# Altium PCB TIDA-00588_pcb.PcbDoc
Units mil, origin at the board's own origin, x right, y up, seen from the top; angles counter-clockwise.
Board outline 4010.03 x 1510.03 mil, 2 copper layers (Top Layer, Bottom Layer), stack 62 mil thick; 90 components, 39 nets, 274 pads, 4 vias.
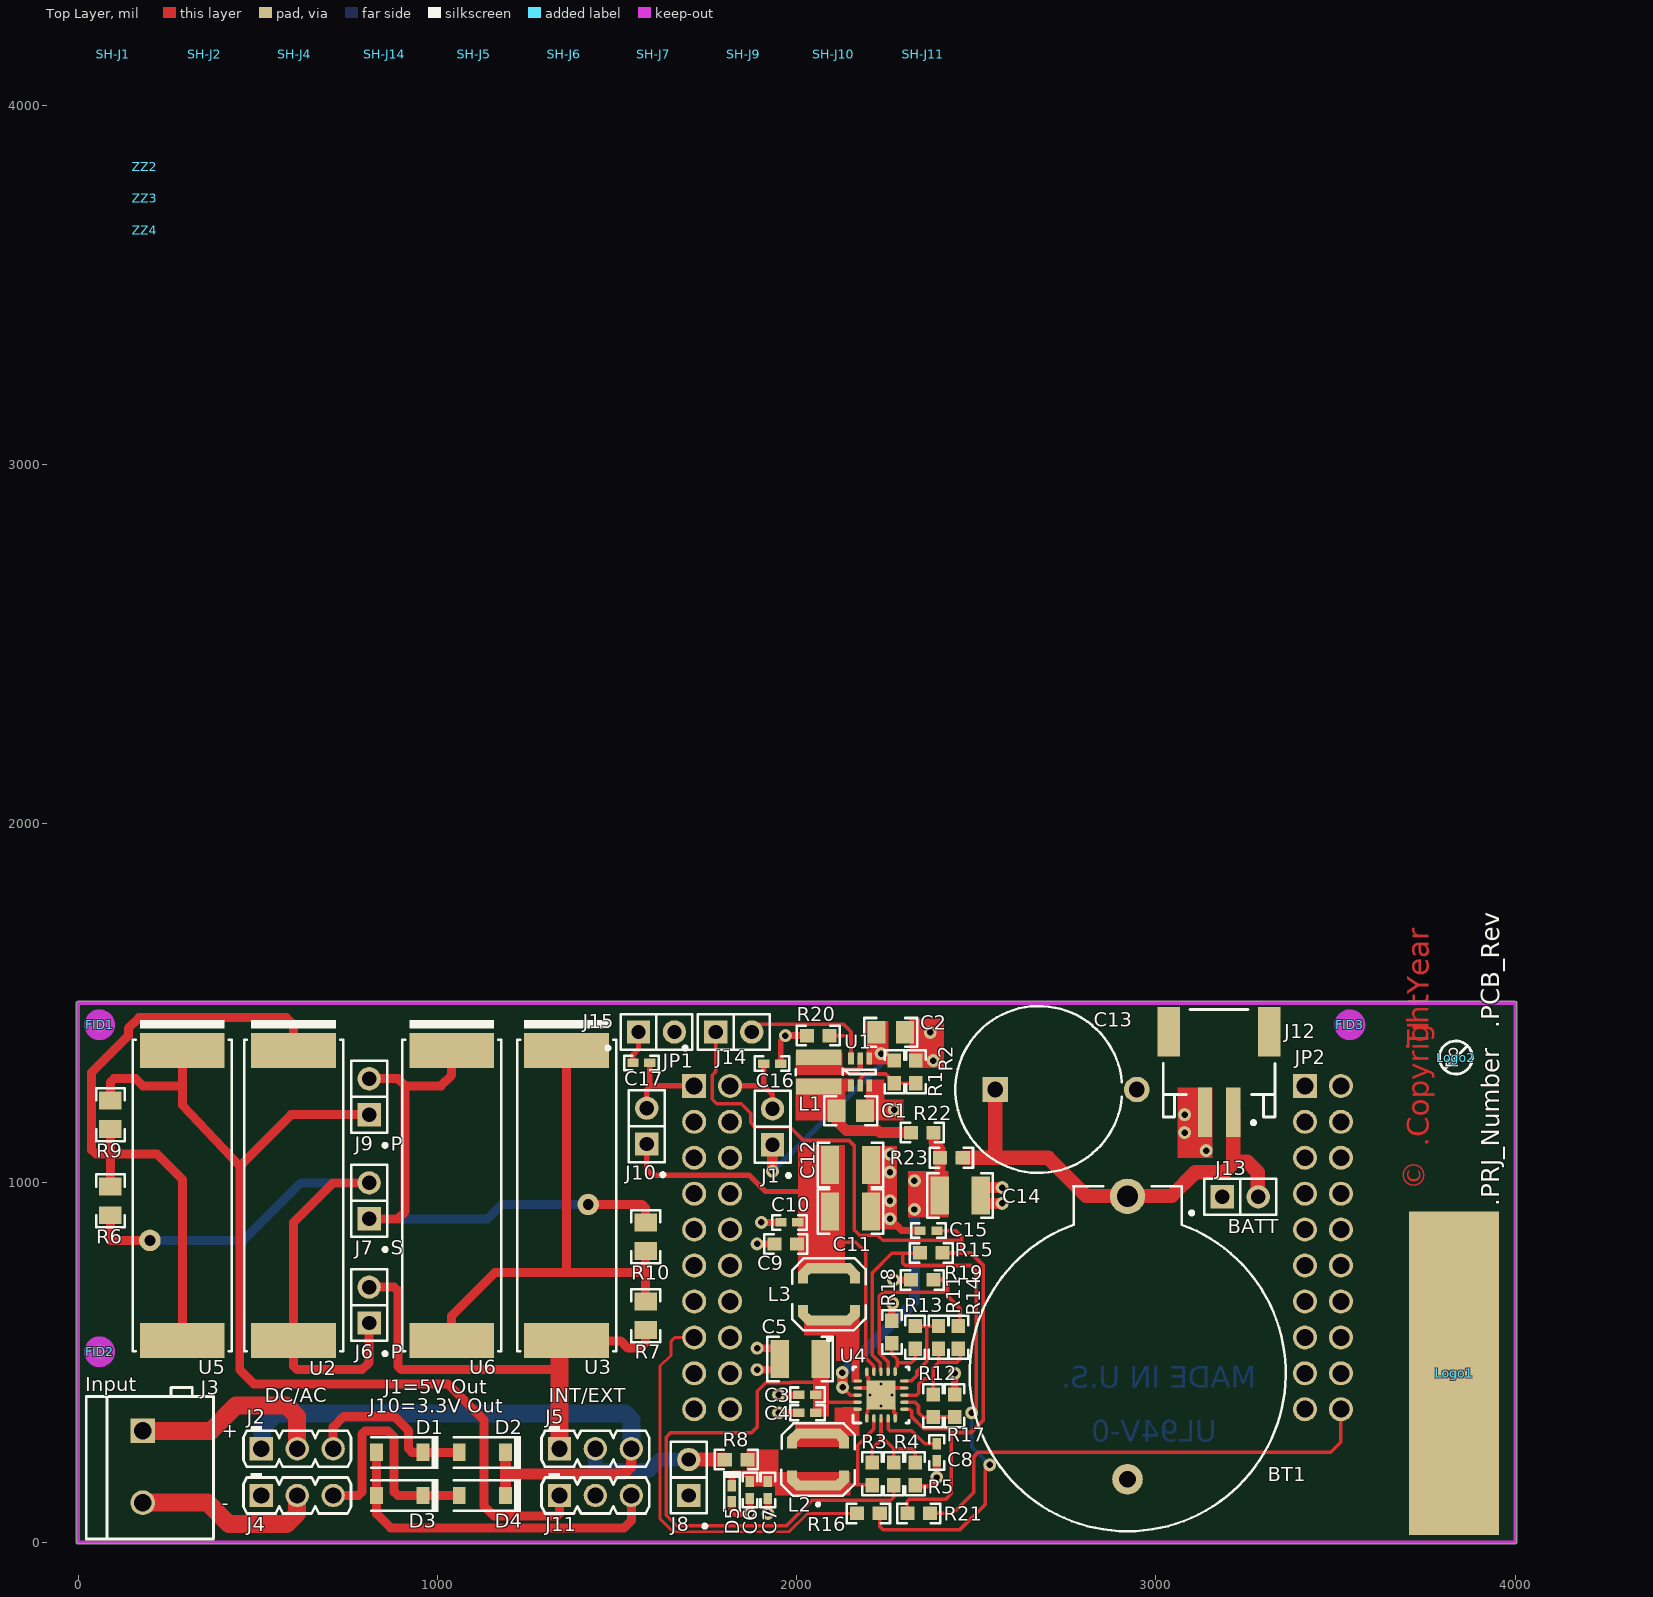
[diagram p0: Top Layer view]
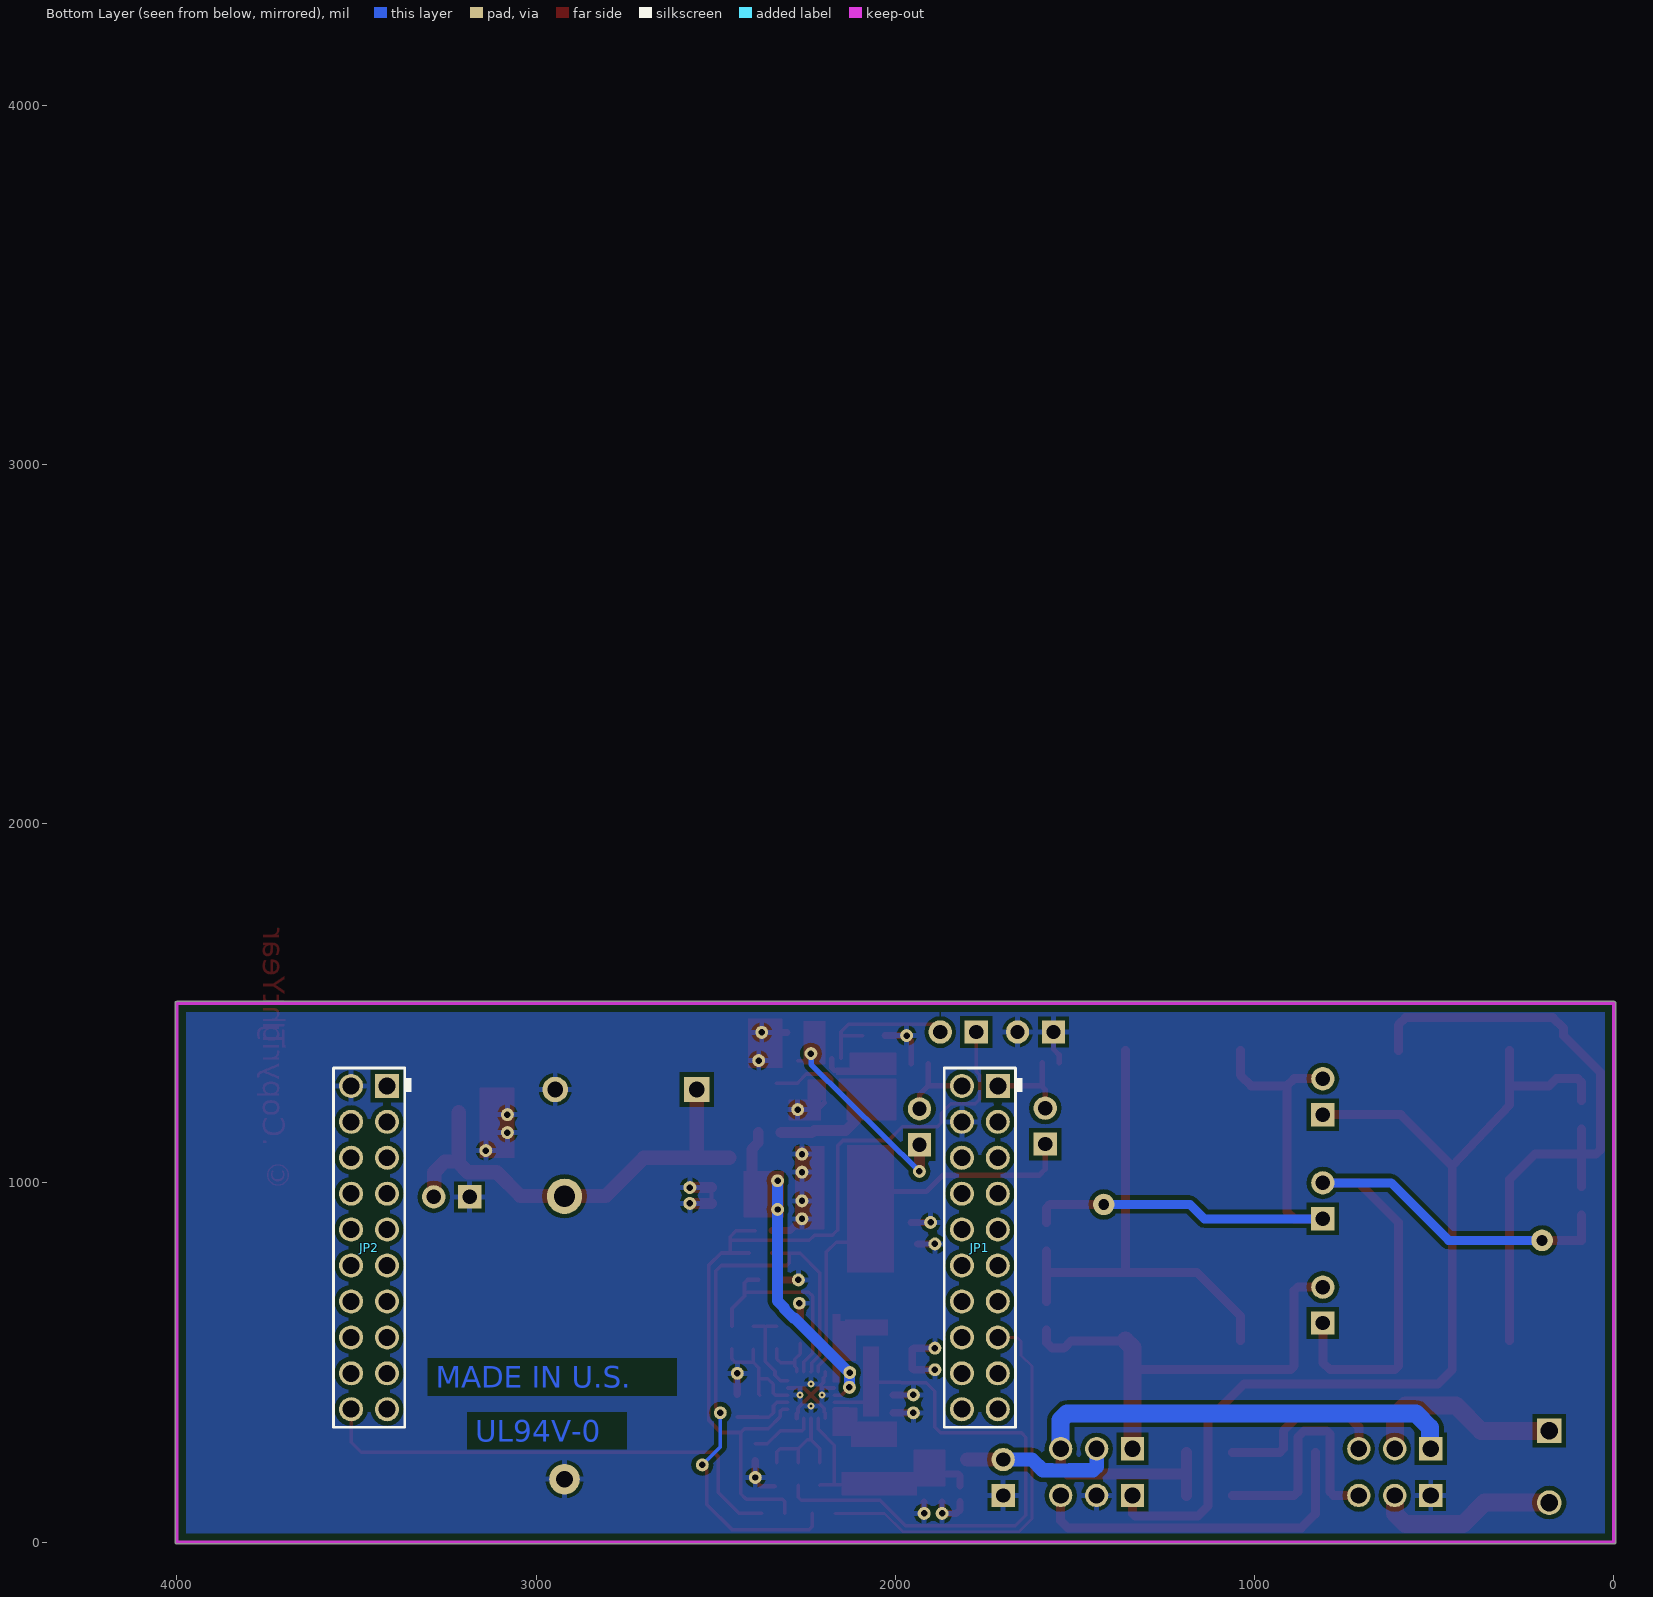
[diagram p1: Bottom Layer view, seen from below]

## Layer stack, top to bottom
Top Solder: solder mask 0.4, Solder Resist, Dk 3.5
Top Layer: signal copper 1.4
Dielectric1: core 59.2, FR-4, Dk 4.8
Bottom Layer: signal copper 1.4
Bottom Solder: solder mask 0.4, Solder Resist, Dk 3.5

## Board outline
0,-5.02 cw(c0,0) -5.01,0 -5.01,1500 cw(c0,1500) 0,1505.01 4000,1505.01 cw(c4000,1500) 4005.02,1500 4005.02,0 cw(c4000,0) 4000,-5.02

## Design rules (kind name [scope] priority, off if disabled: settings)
AcuteAngle [All] p1: minimum=4.50000000000000E+0001 checktracksonly=FALSE
AssemblyTestPointUsage [All] p1: valid=2
Clearance Clearance_Keepouts [((IsTrack Or IsArc) And Not InPoly) And IsFree and IsKeepOut vs ((IsTrack Or IsArc) And Not InPoly) And IsFree and IsKeepOut] p1: gap=0
Clearance Clearance_BoardEdge_MountingHoles [OnCopper and InComponentClass('Mounting Holes') vs IsKeepOut] p2: gap=40
Clearance Clearance_BoardEdge_Poly [OnCopper and InPoly vs IsKeepOut] p3: gap=20
Clearance Clearance_BoardEdge [OnCopper and Not InComponentClass('Logo') and not InComponentClass('FiducialMark') and not InRegion(1000,500,4000,800) and Not IsKeepout vs IsKeepOut] p4: gap=20 except(40: Track-SMDPad Arc-SMDPad SMDPad-SMDPad)
Clearance Clearance_Poly [InPolygon] p5: gap=12
Clearance [All] p6: gap=8
ComponentClearance ComponentClearance_MountingHoles_FiducialMarks [InComponentClass('Mounting Holes') vs InComponentClass('FiducialMark')] p1: gap=50 collisioncheckmode=3 verticalgap=10 showdistances=FALSE
ComponentClearance ComponentClearance_Shunt [InComponentClass('Header') vs InComponentClass('Shunt')] p2: gap=0 collisioncheckmode=3 verticalgap=0 showdistances=FALSE
ComponentClearance ComponentClearance_Logo [InComponentClass('Logo')] p3: gap=50 collisioncheckmode=3 verticalgap=10 showdistances=FALSE
ComponentClearance ComponentClearance_ScrewToNut [(HasFootprint('NY PMS 440 0025 PH')) vs (HasFootprint('Keystone_1902C'))] p4: gap=5 collisioncheckmode=3 verticalgap=10 showdistances=FALSE
ComponentClearance ComponentClearance_MountingHoles [InComponentClass('Mounting Holes')] p5: gap=20 collisioncheckmode=3 verticalgap=100000 showdistances=FALSE
ComponentClearance ComponentClearance_SmallPassives [HasFootprint('0201*') or HasFootprint('0402*') or HasFootprint('0508') or HasFootprint('0603*') or HasFootprint('0612') or HasFootprint('0805*') or HasFootprint('0815*') or HasFootprint('0830*') or HasFootprint('1206*') or HasFootprint('1210*') or HasFootprint('1808*') or HasFootprint('1812*') or HasFootprint('1825*') or HasFootprint('2010*') or HasFootprint('2220*') or HasFootprint('2225*') or HasFootprint('2512*') or HasFootprint('2728*') or HasFootprint('3518*') vs HasFootprint('0201*') or HasFootprint('0402*') or HasFootprint('0508') or HasFootprint('0603*') or HasFootprint('0612') or HasFootprint('0805*') or HasFootprint('0815*') or HasFootprint('0830*') or HasFootprint('1206*') or HasFootprint('1210*') or HasFootprint('1808*') or HasFootprint('1812*') or HasFootprint('1825*') or HasFootprint('2010*') or HasFootprint('2220*') or HasFootprint('2225*') or HasFootprint('2512*') or HasFootprint('2728*') or HasFootprint('3518*')] p6: gap=12 collisioncheckmode=3 verticalgap=12 showdistances=FALSE
ComponentClearance ComponentClearance_THtoSMT [IsThruComponent vs IsSMTComponent] p7: gap=12 collisioncheckmode=3 verticalgap=12 showdistances=FALSE
ComponentClearance ComponentClearance_THtoTH [IsThruComponent vs IsThruComponent] p8: gap=12 collisioncheckmode=3 verticalgap=12 showdistances=FALSE
ComponentClearance [All] p9: gap=12 collisioncheckmode=3 verticalgap=12 showdistances=FALSE
DiffPairsRouting [All] p1: maxlimit=100 minlimit=10 mostfreqgap=10 toplayer_minwidth=15 toplayer_maxwidth=15 toplayer_prefwidth=15 bottomlayer_minwidth=15 bottomlayer_maxwidth=15 bottomlayer_prefwidth=15 maxuncoupledlength=1000
FabricationTestPointUsage TestPointUsage [All] p1: valid=2 allowmultiple=FALSE
FabricationTestpoint Testpoint [All] p1: side=3 testpointundercomponent=TRUE minsize=40 maxsize=100 preferedsize=60 minholesize=0 maxholesize=40 preferedholesize=32 testpointgrid=1 allowsidetop=TRUE allowsidebottom=TRUE usegrid=TRUE gridtolerance=0.01
FanoutControl Fanout_LCC [IsLCC] p1: bgadir=Out bgaviamode=Centered fanoutstyle=Auto fanoutdirection=Alternating viagrid=1 // Fanout_LCC (Default Rule)
FanoutControl Fanout_BGA [IsBGA] p2: bgadir=Out bgaviamode=Centered fanoutstyle=Auto fanoutdirection=Alternating viagrid=1 // Fanout_BGA (Default Rule)
FanoutControl Fanout_Default [All] p4: bgadir=Out bgaviamode=Centered fanoutstyle=Auto fanoutdirection=Alternating viagrid=1 // Fanout_Default (Default Rule)
FanoutControl Fanout_Small [(CompPinCount < 5)] p5: bgadir=Out bgaviamode=Centered fanoutstyle=Auto fanoutdirection=OutThenIn viagrid=1 // Fanout_Small (Default Rule)
HoleSize [All] p1: absolutevalues=TRUE maxlimit=251 minlimit=8 maxpercent=80.000 minpercent=20.000
MinimumAnnularRing MinimumAnnularRing_ThermalPadVias [IsVia and InAnyComponent] p1: minimumring=5.91
MinimumAnnularRing [All] p2: minimumring=9
MinimumSolderMaskSliver MinimumSolderMaskSliver_Logo [InComponentClass('Logo') vs InComponentClass('Logo')] p1: minsoldermaskwidth=0.7
MinimumSolderMaskSliver [All] p2: minsoldermaskwidth=3.94
PlaneConnect [All] p1: planeconnectstyle=Relief reliefexpansion=10 reliefentries=4 reliefconductorwidth=15 reliefairgap=10
PolygonConnect [All] p1: connectstyle=Relief reliefconductorwidth=15 reliefentries=4 polygonreliefangle="90 Angle" airgapwidth=10
RoutingVias ThermalPadVias [IsVia and InAnyComponent] p1: holewidth=7.87 width=19.68 viastyle="Through Hole" minholewidth=7.87 minwidth=19.68 maxholewidth=12.99 maxwidth=23.62
RoutingVias [All] p2: holewidth=16 width=34 viastyle="Through Hole" minholewidth=7.87 minwidth=26 maxholewidth=40 maxwidth=65
SilkToBoardRegionClearance [Not ((IsComment or IsDesignator) And (Hide <> 'False')) and not InRegion(1000,500,4000,800)] p1:
SilkToSilkClearance SilkToSilkClearance_Pb-FreeLogo [(HasFootprint('Pb-Free_Overlay_Medium') OR HasFootprint('Pb-Free_Overlay_Small')) vs (HasFootprint('Pb-Free_Overlay_Medium') OR HasFootprint('Pb-Free_Overlay_Small'))] p1: silktosilkclearance=0
SilkToSilkClearance [All] p2: silktosilkclearance=5
SilkToSolderMaskClearance "Silk to Solder Mask Opening" [All] p1: minsilkscreentomaskgap=1 clearancetoexposedcopper=FALSE
SolderMaskExpansion [All] p1: expansion=1.97
UnpouredPolygon [All] p1: allowunpoured=FALSE
Width [All] p1: maxlimit=100 minlimit=8 preferedwidth=10 checkconnectedcopper=TRUE
14 further rules are at their usual default settings.

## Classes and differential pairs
component class Shunt: SH-J1 SH-J2 SH-J4 SH-J5 SH-J6 SH-J7 SH-J9 SH-J10 SH-J11 SH-J14
component class TIDA-00588_sch: BT1 C1 C2 C3 C4 C5 C6 C7 C8 C9 C10 C11 C12 C13 C14 C15 C16 C17 D1 D2 D3 D4 D5 J1 J2 J3 J4 J5 J6 J7 J8 J9 J10 J11 J12 J13 J14 J15 JP1 JP2 L1 L2 L3 R1 R2 R3 R4 R5 R6 R7 R8 R9 R10 R11 R12 R13 R14 R15 R16 R17 R18 R19 R20 R21 R22 R23 U1 U2 U3 U4 U5 U6
component class Header: J1 J2 J4 J5 J6 J7 J8 J9 J10 J11 J13 J14 J15
component class Logo: Logo1
component class TIDA-00588_hdw: FID1 FID2 FID3 Logo1 Logo2 SH-J1 SH-J2 SH-J4 SH-J5 SH-J6 SH-J7 SH-J9 SH-J10 SH-J11 SH-J14 ZZ2 ZZ3 ZZ4
component class FiducialMark: FID1 FID2 FID3
component class AssemblyNote: ZZ2 ZZ3 ZZ4

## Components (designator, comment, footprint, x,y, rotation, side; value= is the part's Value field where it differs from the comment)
BT1 "BS-7" BAT_BS-7 2921,569 r270 top
C1 "GRM21BR61A106KE19L" 0805_HV 2151,1201 r180 top
C2 "GRM21BR61A106KE19L" 0805_HV 2262,1419 r0 top
C3 "C1005X5R0J475M050BC" 0402 2030,410 r180 top
C4 "GRM155R71A104KA01D" 0402 2030,360 r180 top
C5 "C1210C107M9PACTU" 1210 2010,510 r180 top
C6 "GRM155R71A104KA01D" 0402 1870,145 r270 top
C7 "C1005X5R0J475M050BC" 0402 1920,145 r270 top
C8 "GRM155R61A103KA01D" 0402 2390,250 r270 top
C9 "CL10A226MP8NUNE" 0603 1970,830 r180 top
C10 "GRM155R71A104KA01D" 0402 1980,890 r180 top
C11 "C1210C107M9PACTU" 1210 2150,920 r0 top
C12 "C1210C107M9PACTU" 1210 2150,1050 r0 top
C13 "DX-5R5H473U" DX-H_1150x500 2750,1260 r0 top
C14 "C1210C107M9PACTU" 1210 2455,965 r0 top
C15 "C1005X5R0J105M" 0402 2366.92,867.31 r180 top
C16 "GRM155R71A104KA01D" 0402 1932,1332 r0 top
C17 "GRM155R71A104KA01D" 0402 1568,1334 r180 top
D1 "MBR0520LT1G" SOD-123 895.53,250 r180 top
D2 "MBR0520LT1G" SOD-123 1125.53,250 r180 top
D3 "MBR0520LT1G" SOD-123 895.53,130 r180 top
D4 "MBR0520LT1G" SOD-123 1125.53,130 r180 top
D5 "BZT52C4V7T-7" SOD-523 1820,135 r270 top
FID1 "Fiducial" Fiducial10-20 60,1440 r0 top
FID2 "Fiducial" Fiducial10-20 60,530 r0 top
FID3 "Fiducial" Fiducial10-20 3540,1440 r0 top
J1 "90120-0122" CONN_90120-0122 1933,1156 r90 top
J2 "61300311121" WURTH_61300311121 610,260 r0 top
J3 "ED120/2DS" CONN_ED120-2DS 180,210 r180 top
J4 "61300311121" WURTH_61300311121 610,130 r0 top
J5 "61300311121" WURTH_61300311121 1440,260 r0 top
J6 "90120-0122" CONN_90120-0122 810,660 r90 top
J7 "90120-0122" CONN_90120-0122 810,950 r90 top
J8 "90120-0122" CONN_90120-0122 1700,180 r90 top
J9 "90120-0122" CONN_90120-0122 810,1240 r90 top
J10 "90120-0122" CONN_90120-0122 1583,1158.14 r90 top
J11 "61300311121" WURTH_61300311121 1440,130 r0 top
J12 "S2B-PH-SM4-TB(LF)(SN)" JST_S2B-PH-SM4-TB 3176,1313 r180 top
J13 "90120-0122" CONN_90120-0122 3235,961 r0 top
J14 "90120-0122" CONN_90120-0122 1825.14,1420 r0 top
J15 "90120-0122" CONN_90120-0122 1610,1420 r0 top
JP1 "CRD-081413-A-G" Major_CRD-081413-A-x 1764.96,820 r0 bottom
JP2 "CRD-081413-A-G" Major_CRD-081413-A-x 3464.96,820 r0 bottom
L1 "EPL3015-472MLB" EPL3015 2062,1309 r90 top
L2 "LPS4018-223MLB" LPS4018 2060,230 r90 top
L3 "LPS4018-103MLB" LPS4018 2090,690 r90 top
Logo1 "Texas Instruments" TI_Stacked_SolderMask_Small 3830,470 r90 top
Logo2 "Pb-Free Symbol" Pb-Free_Overlay_Small 3835,1349 r90 top
R1 "CRCW06031M00FKEA" 0603 2272,1309 r90 top
R2 "CRCW0603110KFKEA" 0603 2332,1309 r270 top
R3 "ERJ-3GEY0R00V" 0603 2210,190 r90 top
R4 "ERJ-3GEY0R00V" 0603 2270,190 r270 top
R5 "ERJ-3GEY0R00V" 0603 2330,190 r90 top
R6 "CRCW08050000Z0EA" 0805_HV 90,950 r270 top
R7 "CRCW08050000Z0EA" 0805_HV 1580,630 r270 top
R8 "ERJ-3GEY0R00V" 0603 1831.5,230 r0 top
R9 "CRCW08050000Z0EA" 0805_HV 90,1190 r270 top
R10 "CRCW08050000Z0EA" 0805_HV 1580,850 r270 top
R11 "CRCW0603374KFKEA" 0603 2395,570 r270 top
R12 "CRCW06037M32FKEA" 0603 2380,380 r90 top
R13 "CRCW06038M25FKEA" 0603 2330,570 r90 top
R14 "CRCW06038M25FKEA" 0603 2450,570 r270 top
R15 "ERJ-3GEY0R00V" 0603 2375,805 r180 top
R16 "ERJ-3GEY0R00V" 0603 2200,80 r180 top
R17 "CRCW06035M62FKEA" 0603 2440,380 r270 top
R18 "CRCW06034M53FKEA" 0603 2265,585 r270 top
R19 "CRCW06034M75FKEA" 0603 2350,730 r180 top
R20 "CRCW06031M00FKEA" 0603 2060,1410 r0 top
R21 "ERJ-3GEY0R00V" 0603 2340,80 r0 top
R22 "ERJ-3GEY0R00V" 0603 2350,1140 r180 top
R23 "ERJ-3GEY0R00V" 0603 2431,1070 r180 top
SH-J1 "969102-0000-DA" SNT-100-BK-G 98,4141 r90 top
SH-J2 "969102-0000-DA" SNT-100-BK-G 353,4141 r90 top
SH-J4 "969102-0000-DA" SNT-100-BK-G 603,4141 r90 top
SH-J5 "969102-0000-DA" SNT-100-BK-G 1103,4141 r90 top
SH-J6 "969102-0000-DA" SNT-100-BK-G 1353,4141 r90 top
SH-J7 "969102-0000-DA" SNT-100-BK-G 1603,4141 r90 top
SH-J9 "969102-0000-DA" SNT-100-BK-G 1853,4141 r90 top
SH-J10 "969102-0000-DA" SNT-100-BK-G 2103,4141 r90 top
SH-J11 "969102-0000-DA" SNT-100-BK-G 2353,4141 r90 top
SH-J14 "969102-0000-DA" SNT-100-BK-G 853,4141 r90 top
U1 "TPS61220DCKR" DCK0006A_N 2177,1309 r90 top
U2 "KXOB22-04X3L" KXOB22-04X3 600,965 r90 top
U3 "KXOB22-04X3L" KXOB22-04X3 1360,965 r90 top
U4 "BQ25570RGRR" RGR0020A 2234.96,409.37 r90 top
U5 "KXOB22-04X3L" KXOB22-04X3 290,965 r90 top
U6 "KXOB22-04X3L" KXOB22-04X3 1040,965 r90 top
ZZ2 "This Assembly Note will show in the PcbDoc and associated outputs" AssemblyNote 185,3829.11 r0 top
ZZ3 "This Assembly Note will show in the PcbDoc and associated outputs" AssemblyNote 185,3740.56 r0 top
ZZ4 "This Assembly Note will show in the PcbDoc and associated outputs" AssemblyNote 185,3652 r0 top

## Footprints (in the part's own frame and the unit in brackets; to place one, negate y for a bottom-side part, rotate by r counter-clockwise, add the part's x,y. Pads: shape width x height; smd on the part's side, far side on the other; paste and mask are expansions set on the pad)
0402 [mm] "0402 from SM-752 data"
  rect 0.8x0.6 smd: 1(-0.6,0) 2(0.6,0)
  silkscreen extent -1.22,-0.52 1.22,0.52, body extent -0.55,-0.3 0.55,0.3, height 0.6
0603 [mm] "0603 from SM-752 data"
  rect 1x0.95 smd: 1(-0.8,0) 2(0.8,0)
  silkscreen extent -1.52,-0.69 1.52,0.69, body extent -0.87,-0.47 0.87,0.47, height 0.85
0805_HV [mil] "0805 with 30mil clearance between pads"
  rect 50x63 smd: 1(-40,0) 2(40,0)
  silkscreen extent -74,-40 74,40, body extent -43,-29 43,29, height 43
1210 [mm] "1210 from SM-752 data"
  rect 1.3x2.7 smd: 1(-1.45,0) 2(1.45,0)
  silkscreen extent -2.32,-1.57 2.32,1.57, body extent -1.7,-1.35 1.7,1.35, height 1.35
AssemblyNote [mil] "Assembly Note"
BAT_BS-7 [mm] "Memory Protection Devices CR2032 battery holder"
  round 2.5 hole 1.5: 1(-10,0)
  round 2.17 hole 1.181: 2(10,0)
  silkscreen extent -10.7,-11.16 13.68,11.18, body extent -10.69,-11.16 13.7,11.16, height 9.02
CONN_90120-0122 [mm] "Molex"
  rect 1.65x1.65 hole 1.016 mask+0: 1(-1.27,0)
  round 1.65 hole 1.016 mask+0: 2(1.27,0)
  silkscreen extent -3.56,-1.27 2.54,1.27, body extent -2.54,-1.27 2.54,1.27, height 9.29
CONN_ED120-2DS [mm] "ONSHORE"
  rect 1.75x1.75 hole 1.25: 1(0,-2.54)
  round 1.75 hole 1.25: 2(0,2.54)
  silkscreen extent -5,-5.6 4,5.12, body extent -5,-5.6 4.15,5.12, height 13.1
DCK0006A_N [mm] "SOT23, 6-Leads, Body 2x1.3mm, Pitch 0.65mm, Lead Span 2.1mm, IPC Medium Density"
  rect 0.85x0.4 smd: 1(-0.95,0.65) 2(-0.95,0) 3(-0.95,-0.65) 4(0.95,-0.65) 5(0.95,0) 6(0.95,0.65)
  silkscreen extent -0.15,-1.1 0.15,1.1, body extent -1.14,-1 1.14,1, height 0.94
DX-H_1150x500 [mm] "Elna horizontal SUPERCAP"
  rect 1.8x1.8 hole 1.1: 1(-5,0)
  round 1.8 hole 1.1: 2(5,0)
  silkscreen extent -7.82,-5.9 3.95,5.9, body extent -7.84,-5.91 5.07,5.91, height 5.5
EPL3015 [mm] "COILCRAFT"
  rect 1.12x3.2 smd: 1(-1.04,0) 2(1.04,0)
  silkscreen extent -0.22,-1.68 0.23,1.65, body extent -1.6,-1.6 1.6,1.6, height 1.55
Fiducial10-20 [mm]
  round 1 smd mask+0.5: 1(0,0)
  Top Layer keep-out circle w1.178: c0,0 r0.5
JST_S2B-PH-SM4-TB [mm] "JST Sales America Inc"
  rect 1x3.5 smd paste+0 mask+0.05: 1(-1,2.95) 2(1,2.95)
  rect 1.6x3.5 smd paste+0 mask+0.05: M1(-3.55,-2.75) M2(3.55,-2.75)
  silkscreen extent -3.95,-4.3 3.95,3.79, body extent -3.95,-4.3 3.95,4.3, height 5.62
KXOB22-04X3 [mm] "IXYS"
  rect 2.5x6 smd: 1(-10.25,0) 2(10.25,0)
  silkscreen extent -11,-3.5 12.4,3.5, body extent -11,-3.5 11,3.5, height 1.81
LPS4018 [mil]
  rect 28x123 smd: 1(-72.5,0) 2(72.5,0)
  rect 35.5x28 smd rot 45: 1(-64,64) 2(64.5,-63.5)
  rect 35.5x28 smd rot 135: 1(-64,-64) 2(64,64)
  rect 31.5x28 smd: 1(-46,72.5) 1(-46,-72.5) 2(46,72.5) 2(46,-72.5)
  silkscreen extent -129,-102 100,102, body extent -81,-81 81,81, height 71
Major_CRD-081413-A-x [mm] "Receptacle, 2.54 mm, 10x2, TH"
  rect 1.7x1.7 hole 1.2: 1(-1.27,-11.43)
  round 1.7 hole 1.2: 2(1.27,-11.43) 3(-1.27,-8.89) 4(1.27,-8.89) 5(-1.27,-6.35) 6(1.27,-6.35) 7(-1.27,-3.81) 8(1.27,-3.81) 9(-1.27,-1.27) 10(1.27,-1.27) 11(-1.27,1.27) 12(1.27,1.27) 13(-1.27,3.81) 14(1.27,3.81) 15(-1.27,6.35) 16(1.27,6.35) 17(-1.27,8.89) 18(1.27,8.89) 19(-1.27,11.43) 20(1.27,11.43)
  silkscreen extent -3,-12.71 2.52,12.71, body extent -2.52,-12.71 2.52,12.71, height 8.64
Pb-Free_Overlay_Small [mil]
  silkscreen extent -46,-46 46,46
RGR0020A [mm] "QFN, 20-Leads, Body 3.5x3.5mm, Pitch 0.5mm, Thermal Pad 2.05x2.05mm, TI Recommended"
  oval 0.6x0.24 smd: 1(-1.65,1) 2(-1.65,0.5) 3(-1.65,0) 4(-1.65,-0.5) 5(-1.65,-1) 11(1.65,-1) 12(1.65,-0.5) 13(1.65,0) 14(1.65,0.5) 15(1.65,1)
  oval 0.24x0.6 smd: 6(-1,-1.65) 7(-0.5,-1.65) 8(0,-1.65) 9(0.5,-1.65) 10(1,-1.65) 16(1,1.65) 17(0.5,1.65) 18(0,1.65) 19(-0.5,1.65) 20(-1,1.65)
  rect 2.05x2.05 smd paste-1.025: 21(0,0)
  silkscreen extent -1.97,-1.97 1.97,1.97, body extent -1.83,-1.83 1.83,1.83, height 1.01
SNT-100-BK-G [mil] "Samtec STEP model"
  round 1 on Mech3: 0(0,0)
  body extent -100,-50 100,50, height 344
SOD-123 [mm] "On Semi recommended land pattern"
  rect 0.915x1.22 smd: 1(-1.637,0) 2(1.637,0)
  silkscreen extent -2.74,-1.17 2.03,1.17, body extent -1.93,-0.9 1.93,0.9, height 1.35
SOD-523 [mm] "NXP Semiconductor recommended land pattern, nominal STEP model"
  rect 0.8x0.6 smd paste-0.05: 1(-0.55,0) 2(0.55,0)
  silkscreen extent -1.6,-0.63 1.2,0.64, body extent -0.8,-0.4 0.8,0.4, height 0.72
TI_Stacked_SolderMask_Small [mil]
  rect 900x250 smd paste-125 mask-125: 0(0,0)
WURTH_61300311121 [mm] "Header, 2.54mm, 3x1, TH"
  rect 1.65x1.65 hole 1.15: 1(-2.54,0)
  round 1.65 hole 1.15: 2(0,0) 3(2.54,0)
  silkscreen extent -3.81,-1.27 3.81,1.6, body extent -3.81,-1.27 3.81,1.27, height 8.54

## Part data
BT1: "Battery Holder, CR2032, Retainer clip, TH"
C1 C2: "CAP, CERM, 10 µF, 10 V, +/- 10%, X5R, 0805"
C3 C7: "CAP, CERM, 4.7 µF, 6.3 V, +/- 20%, X5R, 0402"
C4 C6 C10 C16 C17: "CAP, CERM, 0.1 µF, 10 V, +/- 10%, X7R, 0402"
C5 C11 C12 C14: "CAP, CERM, 100 µF, 6.3 V, +/- 20%, X5R, 1210"
C8: "CAP, CERM, 0.01 µF, 10 V, +/- 10%, X5R, 0402"
C9: "CAP, CERM, 22 µF, 10 V, +/- 20%, X5R, 0603"
C13: "CAP, Electric Double Layer, 47000 µF, 5.5 V, +80/-20%, TH"
C15: "CAP, CERM, 1 µF, 6.3 V, +/- 20%, X5R, 0402"
D1 D2 D3 D4: "Diode, Schottky, 20 V, 0.5 A, SOD-123"
D5: "Diode, Zener, 4.7 V, 300 mW, SOD-523"
FID1 FID2 FID3: "Fiducial mark.  There is nothing to buy or mount."
J1 J6 J7 J8 J9 J10 J13 J14 J15: "Header, 100mil, 2x1, Tin, TH"
J2 J4 J5 J11: "Header, 2.54 mm, 3x1, Gold, TH"
J3: "TERMINAL BLOCK 5.08MM VERT 2POS, TH"
J12: "Header (shrouded), 2mm, 2x1, R/A, SMT"
JP1 JP2: "Receptacle, 2.54 mm, 10x2, Gold, TH"
L1: "Inductor, Shielded, Ferrite, 4.7 µH, 1.2 A, 0.14 ohm, SMD"
L2: "Inductor, Shielded Drum Core, Ferrite, 22 µH, 0.83 A, 0.36 ohm, SMD"
L3: "Inductor, Shielded Drum Core, Ferrite, 10 µH, 1.25 A, 0.2 ohm, SMD"
Logo1: library part TI_Logo, "Texas Instrument Corporate Signature"
Logo2: library part Pb-Free
R1 R20: "RES, 1.00 M, 1%, 0.1 W, 0603"
R2: "RES, 110 k, 1%, 0.1 W, 0603"
R3 R4 R5 R8 R15 R16 R21 R22 R23: "RES, 0, 5%, 0.1 W, 0603"
R6 R7 R9 R10: "RES, 0, 5%, 0.125 W, 0805"
R11: "RES, 374 k, 1%, 0.1 W, 0603"
R12: "RES, 7.32 M, 1%, 0.1 W, 0603"
R13 R14: "RES, 8.25 M, 1%, 0.1 W, 0603"
R17: "RES, 5.62 M, 1%, 0.1 W, 0603"
R18: "RES, 4.53 M, 1%, 0.1 W, 0603"
R19: "RES, 4.75 M, 1%, 0.1 W, 0603"
SH-J1 SH-J2 SH-J4 SH-J5 SH-J6 SH-J7 SH-J9 SH-J10 SH-J11 SH-J14: "Shunt, 100mil, Gold plated, Black"
U1: "LOW INPUT VOLTAGE STEP-UP CONVERTER IN 6 PIN SC-70 PACKAGE, DCK0006A"
U2 U3 U5 U6: "MONOCRYSTALLINE SOLAR CELL, 22MM X 7MM, SMD"
U4: "Ultra Low Power Harvester Power Management IC with Boost Charger, and Nano-Powered Buck Converter, RGR0020A"
ZZ2 ZZ3 ZZ4: library part AssemblyNote

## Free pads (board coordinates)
  round 60 hole 30: 0(200,840) 0(1420,940)
  round 36 hole 18: 1(1870,80) 1(1890,480) 1(1890,540) 1(1890,830) 1(1902,890) 1(1920,80) 1(1933,1032) 1(1950,360) 1(1950,410) 1(1968.98,1410) 1(2127,472) 1(2128,430.88) 1(2235,1360) 1(2260,900) 1(2260,950) 1(2260,1030) 1(2260,1080) 1(2267.58,665) 1(2270,730) 1(2272,1204) 1(2328,926) 1(2328,1006) 1(2372,1419) 1(2380.5,1340.5) 1(2390,180) 1(2440,470) 1(2487.42,360) 1(2537.42,215) 1(2572.09,942.91) 1(2572.09,987.09) 1(3080,1140) 1(3080,1190) 1(3140,1090)

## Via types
v1: diameter 19.68, hole 7.87, Top Layer to Bottom Layer, 4 vias

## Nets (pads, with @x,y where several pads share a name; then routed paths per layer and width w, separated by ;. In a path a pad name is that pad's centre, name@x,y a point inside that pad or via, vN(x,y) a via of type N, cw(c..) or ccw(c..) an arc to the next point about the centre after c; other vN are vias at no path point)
+3.3V: C17.1 J10.2 JP1.1 | length 253.3
  Top Layer w15: J10.2 1583,1260 1591.62,1268.62 ; C17.1 1591.62,1268.62 ; JP1.1 1593,1270 1591.62,1268.62
+5V: C16.1 J1.2 JP1.2 | length 230
  Top Layer w15: JP1.2 1908,1270 ; C16.1 1908.38,1270.38 1908,1270 ; J1.2 1933,1245.76 1908.76,1270 1908,1270
GND: BT1.2 C1.1 C2.2 C3.2 C4.2 C5.2 C6.2 C7.2 C8.2 C9.2 C10.2 C11.2 C12.2 C13.2 C14.2 C15.2 C16.2 C17.2 D5.2 J4.1 J8.1 J11.2 J12.2 J13.1 J15.1 J15.2 JP1.4 JP2.2 pad.1@1870,80 pad.1@1890,480 pad.1@1890,540 pad.1@1890,830 pad.1@1902,890 pad.1@1920,80 pad.1@1950,360 pad.1@1950,410 pad.1@1968.98,1410 pad.1@2260,900 pad.1@2260,950 pad.1@2260,1030 pad.1@2260,1080 pad.1@2267.58,665 pad.1@2270,730 pad.1@2272,1204 pad.1@2372,1419 pad.1@2380.5,1340.5 pad.1@2390,180 pad.1@2440,470 pad.1@2572.09,942.91 pad.1@2572.09,987.09 pad.1@3080,1140 pad.1@3080,1190 pad.1@3140,1090 R2.1 R5.1 R17.1 R18.1 R19.2 R20.1 U1.3 U4.1 U4.5 U4.9 U4.15 U4.17 U4.21 | length 2346.2
  Top Layer w10: U4.17 U4.21@2215.28,429.06 ; U4.1 2195.59,360.16 2198.54,363.11 2198.54,372.95 U4.21 ; U4.15 2195.59,461.86 2200,457.45 2200,444.33 U4.21@2215.28,429.06 ; U4.9 2254.65,429.06 U4.21 ; U4.21@2215.28,429.06 U4.21
  Top Layer w12: U4.21 2271.31,373.02 2271.31,361.31 2274.33,358.29 U4.5 ; R5.1@2335.88,155.54 2375.88,155.54 2390,169.66 pad.1@2390,180 ; C14.2@2512.09,942.91 C14.2 C14.2@2512.09,987.09
  Top Layer w15: C17.2 1544.38,1356.38 1560,1372 J15.1 ; C16.2 1955.62,1395.62 pad.1@1970,1410 ; C1.1@2197.59,1223.41 2217,1204 ; R2.1 pad.1@2380.5,1340.5
  Top Layer w20: D5.2 1820,87.76 1822.24,87.76 1830,80 1870,80 C6.2@1870,111.38 ; pad.1@1890,480 1950,480 1952.91,482.91 C5.2 1952.91,537.09 1950,540 pad.1@1890,540 ; pad.1@1890,830 C9.2 ; pad.1@1910,890 C10.2 ; pad.1@1920,80 C7.2@1920,111.38 ; pad.1@1950,360 C4.2 ; pad.1@1950,410 C3.2 ; pad.1@1970,1410 R20.1 ; pad.1@2260,950 2210,950 2207.09,947.09 C11.2 2207.09,902.91 2210,900 2260,900 2292.69,867.31 C15.2 ; pad.1@2260,1030 2210,1030 2207.09,1032.91 C12.2 2207.09,1077.09 2210,1080 pad.1@2260,1080 ; R18.1@2265,611.5 2265,662.42 pad.1@2267.58,665 ; pad.1@2270,730 R19.2 ; C2.2 pad.1@2372,1419 ; pad.1@2390,180 C8.2 ; R17.1 pad.1@2440,470 ; pad.1@3080,1140 3130.87,1140 J12.2@3140.87,1150 ; pad.1@3080,1190 J12.2@3136.46,1190 ; pad.1@3140,1090 3140.87,1090.87 J12.2@3140.87,1150 ; J12.2@3140.87,1195.59 J12.2@3140.87,1150
  Top Layer w30: C14.2@2512.09,942.91 pad.1@2572.09,942.91 ; C14.2@2512.09,987.09 pad.1@2572.09,987.09
  other v1: 2234.96,378.86 2204.45,409.37 2265.47,409.37 2234.96,439.88
NetBT1_1: BT1.1 C13.1 J12.1 J13.2 R23.1 | length 1313.1
  Top Layer w40: R23.1 2553.15,1070 ; C13.1 2553.15,1070 ; 3215.37,1060.87 J12.1 ; 3283.61,1030 3254,1059.61 3219.61,1059.61 3190,1030 3110,1030 3043.7,963.7 2806.3,963.7 2700,1070 2553.15,1070 ; J13.2@3284,959 3284,1029
NetC1_2: C1.2 L1.1 R22.2 U1.1 | length 249.2
  Top Layer w30: C1.2 2111,1173 2138,1146 2226,1146 2232,1140 R22.2
NetC2_1: C2.1 J1.1 pad.1@1933,1032 pad.1@2235,1360 R1.2 U1.4 | length 658.9
  Top Layer w10: C2.1 2217.75,1414.75 2217.75,1346.4 2223.65,1340.5 R1.2
  Top Layer w30: pad.1@1933,1032 J1.1
  Bottom Layer w15: pad.1@1933,1032 2234.4,1330 pad.1@2235,1360
NetC3_1: C3.1 C4.1 C5.1 R4.2 U4.19 | length 1713.7
  Top Layer w10: C4.1 2070.63,360 ; C3.1 2080,410 2080,437.77 2067.09,450.68 C5.1 ; 2060,445 1985.04,445 1983.89,443.85 1914.32,443.85 1890.47,420 1890.47,320.47 1875,305 1650,305 1637,292 1637,75 1666,46 1971.96,46 2042.96,117 2262,117 2270,125 R4.2 ; 2078,389.5 2078.18,389.68 U4.19
NetC6_1: C6.1 C7.1 D5.1 L2.1 R3.1 R8.2 U4.2 | length 435.2
  Top Layer w10: L2.1@2060,157.5 2062.5,160 2170,160 ; R3.1 2208.5,160 2170,160 ; U4.2 2215.28,315.28 2170,270 2170,160
  Top Layer w20: D5.1 1820,185 1825,190 1870,190
NetC8_1: C8.1 U4.4 | length 181.7
  Top Layer w10: U4.4 2254.65,315.34 2259.99,310 2320,310 2356.38,273.62 C8.1
NetC9_1: C9.1 C10.1 C11.1 C12.1 J10.1 L3.2 U4.14 | length 1078.6
  Top Layer w10: C11.1 2092.91,842.09 2100,835 2165,835 2193,807 2193,512 2214.61,490.39 2215.28,490.39 U4.14
  Top Layer w15: J10.1 1583,1038 1600,1021 1869,1021 1914,976 2031,976
NetC14_1: C14.1 pad.1@2127,472 pad.1@2128,430.88 pad.1@2328,926 pad.1@2328,1006 R22.1 R23.2 U4.18 | length 1081.9
  Top Layer w10: pad.1@2128,430.88 2149.51,409.37 U4.18
  Top Layer w30: pad.1@2128,430.88 2127,472 pad.1@2128,472 ; pad.1@2328,928 2328,965 ; pad.1@2328,1006 2328,965 ; R22.1 2381.5,1112.7 2399.5,1094.7 R23.2 C14.1@2399.5,966.59 ; C14.1 2328,965
  Bottom Layer w30: pad.1@2128,430.88 2128,471 2281,624 2284.57,624 2308.58,648.02 2308.58,651.58 2328,671 2328,926 pad.1@2328,1006
NetC15_1: C15.1 J14.1 R15.1 R21.1 U4.6 | length 2486.4
  Top Layer w10: J14.1 1775.14,1310.14 1765,1300 1765,1233 1778,1220 1846,1220 1872,1194 1872,1167 1883,1156 1981,1156 2019,1118 2146,1118 2160,1104 2160,870 2168.5,861.5 ; 2168.5,861.47 2176.11,853.85 2226.15,853.85 2240,840 2460,840 ; U4.6 2315,370 2320,365 2320,350 2354.18,315.82 2420,315.82 2430.65,305.17 ; R21.1 2308.5,113.5 2315,120 2415.65,120 2430.65,135 2430.65,305.17 ; C15.1 2442.66,867.31 2460,849.97 2460,840 ; R15.1 2460,805 ; 2430.65,305.17 2485.17,305.17 2520,340 2520,770 2485,805 2460,805 ; 2460,805 2460,840
NetD1_1: D1.1 D2.2 J2.3 | length 494.2
  Top Layer w25: J2.3 710,320 740,350 880,350 920,310 920,260 930,250 D1.1 D2.2
NetD1_2: D1.2 D3.2 J11.3 | length 974.4
  Top Layer w25: D1.2 D3.2 831.06,78.94 870,40 1520,40 1540,60 J11.3
NetD2_1: D2.1 D4.1 J2.1 J5.3 | length 1719.7
  Top Layer w30: D4.1 1190,190 ; D2.1 1190,190 ; J5.3 1540,210 1520,190 1190,190
  Bottom Layer w50: J2.1 511.57,261.57 511.57,318.57 551,358 1522,358 1540,340 J5.3
NetD3_1: D3.1 D4.2 J4.3 | length 683.2
  Top Layer w25: J4.3 780,130 790,140 790,300 800,310 862.5,310 880,292.5 880,140 890,130 D3.1 D4.2
NetJ2_2: J2.2 J3.1 | length 561.4
  Top Layer w50: J3.1 370,310 440,380 580,380 610,350 J2.2
NetJ3_2: J3.2 J4.2 | length 517.3
  Top Layer w50: J3.2 360,110 420,50 580,50 610,80 J4.2
NetJ5_1: J5.1 J6.2 R7.2 U3.1 | length 1327.5
  Top Layer w25: J6.2 880,710 890,700 890,490 900,480 1340,480 ; U3.1 1361.46,560 1510,560 1530,540 1564,540 1580,556 R7.2
  Top Layer w50: J5.1 1340,480 1340,541.46 U3.1
NetJ5_2: J5.2 J8.2 R8.1 | length 427
  Top Layer w40: J8.2 R8.1
  Bottom Layer w40: J5.2 1440,210.01 1450.01,200 1514.47,200 1514.95,199.52 1565.05,199.52 1565.53,200 1590,200 1620,230 J8.2
NetJ6_1: J6.1 J7.2 pad.0@200,840 R6.2 U2.1 | length 1844.3
  Top Layer w25: R6.2 90,840 pad.0@200,840 ; J6.1 810,500 790,480 610,480 600,490 U2.1 600,890 710,1000 J7.2
  Bottom Layer w25: pad.0@200,840 460,840 620,1000 J7.2
NetJ7_1: J7.1 J9.2 pad.0@1420,940 R10.1 U6.2 | length 1608.2
  Top Layer w25: J7.1 890,900 910,920 910,1270 ; J9.2 890,1290 910,1270 ; U6.2 1040,1300 1010,1270 910,1270 ; pad.0@1420,940 1570,940 1580,930 R10.1
  Bottom Layer w25: J7.1 1140,900 1180,940 pad.0@1420,940
NetJ9_1: J9.1 J11.1 R9.1 U5.2 | length 2885.7
  Top Layer w25: R9.1 90,1280 100,1290 160,1290 180,1270 290,1270 ; U5.2 290,1270 ; J9.1 593.03,1190 450,1046.97 ; J11.1 1340,80 1333,73 1157,73 1130,100 1130,340 1030,440 490,440 450,480 450,1046.97 ; 290,1270 290,1216.97 450,1046.97
NetJ14_2: J14.2 R20.2 U1.6 | length 468.7
  Top Layer w10: R20.2 2150.41,1410 2151.41,1411 ; U1.6 2151.41,1411 ; J14.2@1897.54,1441.7 2130.3,1441.7 2151.41,1420.59 2151.41,1411 ; J14.2@1897.54,1441.7 1873.17,1422.5 1870,1420 1891.7,1441.7 J14.2@1897.54,1441.7
NetL1_2: L1.2 U1.5 | length 138.4
  Top Layer w12: L1.2@2040,1349.37 L1.2@2097.48,1349.37
  Top Layer w15: 2127,1309 2156.89,1309 2160.89,1313 2170,1313 2177,1320 U1.5
NetL2_2: L2.2 U4.20 | length 159.9
  Top Layer w12: L2.2@2060,302.5 2060,320 2070.5,330.5 2110.5,330.5 2120,340 2120,360 2130,370 U4.20
NetL3_1: L3.1 U4.16
NetR1_1: R1.1 R2.2 U1.2 | length 190.5
  Top Layer w10: U1.2 2177,1289.32 2180.18,1292.5 2180.18,1293.38 2187.8,1301 2188.68,1301 2190.78,1303.09 2248.02,1303.09 2272,1279.12 R1.1 R2.2
NetR3_2: R3.2 R4.1 R5.2 U4.3 | length 310.4
  Top Layer w10: R3.2 2210,260 2234.96,284.96 ; U4.3 2234.96,284.96 ; R4.1 2270,260 ; R5.2 2330,251.02 2321.02,260 2270,260 ; 2234.96,284.96 2245.04,284.96 2270,260
NetR6_1: R6.1 R9.2 U2.2 U5.1 | length 1826.9
  Top Layer w25: R6.1 90,1080 ; R9.2 90,1080 ; U5.1 290,1010 220,1080 90,1080 ; U2.2 600,1440 580,1460 170,1460 140,1430 140,1410 38,1308 38,1092 50,1080 90,1080
NetR7_1: R7.1 R10.2 U3.2 U6.1 | length 1416.8
  Top Layer w25: U6.1 1040,630 1160,750 1360,750 ; U3.2 1360,750 ; R7.1 1580,750 ; R10.2 1580,750 ; 1360,750 1580,750
NetR11_1: R11.1 R13.2 U4.10 | length 254.2
  Top Layer w10: U4.10 2318.74,448.74 2335,465 2335,475.87 2361.7,502.57 2361.7,596.84 ; R13.2 2357.05,601.5 2361.7,596.84 ; R11.1 2365.3,601.5 2361.7,597.9 2361.7,596.84
NetR11_2: R11.2 R12.2 R14.2 U4.8 | length 341.1
  Top Layer w10: U4.8 2334.37,409.37 2340,415 2340,440 2355,455 2380,455 ; R12.2@2377.87,409.37 R12.2 2380,455 ; R11.2@2396,537.5 2396,501 ; R14.2@2455,538.5 2455,510.02 2447.02,502.04 2447.02,501 2396,501 ; 2380,455 2380,485 2396,501
NetR12_1: R12.1 R17.2 U4.7 | length 169.5
  Top Layer w10: U4.7 2329.68,389.68 2339.37,380 2339.37,360.63 2352.73,347.27 2378.76,347.27 R12.1 R17.2
NetR13_1: R13.1 R18.2 U4.11 | length 170.6
  Top Layer w10: R18.2 2265,523.98 2280,508.98 2280,499.49 ; U4.11 2274.33,484.33 2280,490 2280,499.49 ; R13.1 2330,510.05 2319.44,499.49 2280,499.49
NetR14_1: R14.1 R19.1 U4.12 | length 591
  Top Layer w10: U4.12 2254.65,501.94 2230,526.58 2230,685 2241,696 2419,696
  Top Layer w12: R19.1 2411.5,730 2420,721.5 2420,685 2455,650 R14.1@2455,601.5
NetR15_2: pad.1@2487.42,360 pad.1@2537.42,215 R15.2 R16.1 U4.13 | length 1712.6
  Top Layer w10: R16.1 2231.5,43.5 2240,35 2455,35 2525,105 2525,200 pad.1@2535,210 ; U4.13 2233.28,476.02 2233.28,497.85 2211.13,520 2211.13,749.87 2265,803.75 2295,803.75 ; R15.2 2342.25,803.75 2295,803.75 ; pad.1@2490,365 2500,375 2500,755 2485,770 2302.72,770 2295,777.72 2295,803.75
  Bottom Layer w10: pad.1@2487.42,360 2487.42,265 pad.1@2537.42,215
VBAT_OK: JP1.15 R16.2 | length 1160.5
  Top Layer w8: JP1.15 1661,570 1650,559 1650,520 1620,490 1620,65 1656,29 1979,29 2030,80 R16.2
VOUT_EN: JP2.20 R21.2 | length 1376.1
  Top Layer w10: R21.2 2435,80 2493.65,138.65 2493.65,238.65 2505,250 3487,250 3514.96,277.96 JP2.20
pads on no net: FID1.1 FID2.1 FID3.1 J12.M1 J12.M2 JP1.3 JP1.5 JP1.6 JP1.7 JP1.8 JP1.9 JP1.10 JP1.11 JP1.12 JP1.13 JP1.14 JP1.16 JP1.17 JP1.18 JP1.19 JP1.20 JP2.1 JP2.3 JP2.4 JP2.5 JP2.6 JP2.7 JP2.8 JP2.9 JP2.10 JP2.11 JP2.12 JP2.13 JP2.14 JP2.15 JP2.16 JP2.17 JP2.18 JP2.19 Logo1.0 SH-J1.0 SH-J2.0 SH-J4.0 SH-J5.0 SH-J6.0 SH-J7.0 SH-J9.0 SH-J10.0 SH-J11.0 SH-J14.0

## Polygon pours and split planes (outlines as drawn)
GND on Bottom Layer "Bottom Layer-gnd" (solid, remove dead copper, pour order 4): 10,1490 10,10 3990,10 3990,1490 10,1490

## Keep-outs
Keep-Out Layer:
  lines w10: 0,0 4000,0 ; 0,0 0,1500 ; 0,0 4000,0 ; 0,1500 4000,1500 ; 0,1500 4000,1500 ; 4000,0 4000,1500 ; 4000,0 4000,1500
  text ".Layer_Name" at 577,-858.49 h60

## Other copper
Top Layer:
  rectangle net NetC14_1: 2310,903 2423,1033
  rectangle net NetC1_2: 2123.85,1254 2159,1290
  rectangle net NetC1_2: 1997,1173 2136,1290
  rectangle net GND: 2314,1320 2410,1457
  rectangle net NetC2_1: 2194,1330 2256,1450
  rectangle net GND: 3060.03,1070 3158,1265
  rectangle net NetL2_2: 1996,265 2123.5,335.25
  rectangle net NetL2_2: 2105,295 2175,375
  rectangle net NetC6_1: 1860,155 1950,258.54
  rectangle net NetC6_1: 1940.5,130 2150,195
  rectangle net NetL3_1: 2153,445 2175,635
  rectangle net NetL3_1: 2110,504 2155,615
  rectangle net NetL3_1: 2020,575 2140,620
  rectangle net NetC9_1: 2004,750 2135,1105
  rectangle net NetC3_1: 2045,350 2090,545
  rectangle net NetL1_2: 1996.71,1300 2166,1321
  rectangle net NetL1_2: 1996.71,1310 2128,1363.13
  rectangle net GND: 2197.24,870 2280,1103.15
  rectangle net GND: 2207,1174 2297,1232.54
  rectangle net GND: 2193.18,1229 2244.73,1288
  text "TI" at 3760,1376 h60 r90
  text ".CopyrightYear" at 3760,1100 h60 r90
  text "©" at 3770,980 h105 r90
  text ".Layer_Name" at 577,-858.49 h60
Bottom Layer:
  text "MADE IN U.S." at 3280,430 h60
  text "UL94V-0" at 3170,280 h60
  text ".Layer_Name" at 577,-858.49 h60

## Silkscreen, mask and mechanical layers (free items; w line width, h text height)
Top Overlay:
  text ".PCB_Rev" at 3956,1431 h50 r90
  text "P" at 870,1090 h40
  text ".PRJ_Number" at 3956,935 h50 r90
  text "BATT" at 3200,860 h40
  text "S" at 870,800 h40
  text "P" at 870,510 h40
  text "Input" at 20,420 h40
  text "J1=5V Out" at 852,413 h40
  text "DC/AC" at 520,390 h40
  text "INT/EXT" at 1310,390 h40
  text "J10=3.3V Out" at 810,360 h40
  text "+" at 400,290 h40
  text "-" at 400,90 h40
  text ".Layer_Name" at 577,-858.49 h60
Bottom Overlay:
  text ".Layer_Name" at 577,-858.49 h60
Top Paste:
  text ".Layer_Name" at 577,-858.49 h60
Bottom Paste:
  text ".Layer_Name" at 577,-858.49 h60
Top Solder:
  text ".Layer_Name" at 577,-858.49 h60
  text ".Layer_Name" at 577,-858.49 h60
Bottom Solder:
  text ".Layer_Name" at 577,-858.49 h60
Drill Guide:
  text ".Layer_Name" at 577,-858.49 h60
M1 Board Outline:
  lines w10: 0,0 4000,0 4000,1500 0,1500 0,0
  text ".Layer_Name" at 577,-858.49 h60
M2 Board Dimensions:
  rectangle: 0,-275 125,-150
  rectangle: 125,-400 500,-275
  lines w7: 0,-275 1000,-275 ; 125,-400 125,-150 ; 250,-400 250,-150 ; 500,-400 500,-150 ; 750,-400 750,-150 ; 0,-400 1000,-400 1000,-150 0,-150 0,-400
  text ".Layer_Name" at 577,-858.49 h60
M3 3D STEP Top:
  text ".Layer_Name" at 577,-858.49 h60
M4 3D STEP Bottom:
  text ".Layer_Name" at 577,-858.49 h60
M5 Assembly Top:
  lines w10: -292,-930.17 6308,-930.17 ; -292,-726.83 6310,-726.83 ; -292,-523.5 -292,-1133.5 3713,-1133.5 6310,-1133.5 6310,-523.5 -291.5,-523.5 -291.5,-1133.5 1284,-1133.5 ; 2173,-1133.5 2173,-523.5 ; 3440,-726.83 3440,-523.5 ; 4280,-726.83 4280,-523.5 ; 4902,-1140 4902,-937.17
  text "SHUNTS - See schematic for shunt population" at 50,4390 h40
  text "COMPONENTS MARKED 'DNP' SHOULD NOT BE POPULATED." at 1153.5,-318.5 h60
  text "ASSEMBLY VARIANT:" at 1153,-434 h60
  text ".VariantName" at 2189,-434 h60
  text "PCB VIEWED FROM TOP SIDE" at -228.5,-655.67 h60
  text "BOARD #:" at 2248,-655.67 h60
  text ".PRJ_Number" at 2793.5,-655.67 h60
  text "REV:" at 3638,-655.67 h60
  text ".PCB_Rev" at 3929.5,-655.67 h60
  text "SVN REV:" at 4476,-655.67 h60
  text ".VersionControl_RevNumber" at 4982,-655.67 h60
  text "PLOT NAME =" at -228.5,-1064.34 h60
  text ".plot_File_Name" at 577,-1064.34 h60
  text "GENERATED    :" at 2250,-1064.34 h60
  text ".Print_Date" at 3119.5,-1064.34 h60
  text ".Print_Time" at 3848.5,-1064.34 h60
  text "TEXAS INSTRUMENTS" at 5113,-1064.34 h60
M6 Assembly Bottom:
  lines w10: -292.5,-727.33 6309.5,-727.33 ; -290.5,-930.67 6309.5,-930.67 ; 1115.5,-1140.5 1115.5,-937.67 ; 1737.5,-727.33 1737.5,-524 ; 2577.5,-727.33 2577.5,-524 ; 3844.5,-1134 3844.5,-524 ; 4733.5,-1134 6309,-1134 6309,-524 -292.5,-524 -292.5,-1134 2304.5,-1134 6309.5,-1134 6309.5,-524
  text "COMPONENTS MARKED 'DNP' SHOULD NOT BE POPULATED." at 6102,-318 h60
  text ".VariantName" at 5058,-434 h60
  text "ASSEMBLY VARIANT:" at 6097,-434 h60
  text ".VersionControl_RevNumber" at 1035.5,-656.17 h60
  text "SVN REV:" at 1541.5,-656.17 h60
  text ".PCB_Rev" at 2088,-656.17 h60
  text "REV:" at 2379.5,-656.17 h60
  text ".PRJ_Number" at 3224,-656.17 h60
  text "BOARD #:" at 3769.5,-656.17 h60
  text "PCB VIEWED FROM BOTTOM SIDE" at 6246,-656.17 h60
  text "TEXAS INSTRUMENTS" at 904.5,-1064.84 h60
  text ".Print_Time" at 2169,-1064.84 h60
  text ".Print_Date" at 2898,-1064.84 h60
  text "GENERATED    :" at 3767.5,-1064.84 h60
  text ".plot_File_Name" at 5440.5,-1064.84 h60
  text "PLOT NAME =" at 6246,-1064.84 h60
M9 Title Sheet:
  drawing of 57 lines, arcs and shapes, not listed
  text "1" at 739.84,8036.5 h70
  text "2" at 3235.5,8036.5 h70
  text "3" at 5724.84,8036.5 h70
  text "4" at 8231.51,8036.5 h70
  text "5" at 10730.5,8036.5 h70
  text "6" at 13235.5,8036.5 h70
  text "A" at -416.5,6893.5 h70
  text "A" at 14383.5,6893.5 h70
  text "B" at -416.5,4513.5 h70
  text "B" at 14383.5,4513.5 h70
  text "C" at -416.5,2138.5 h70
  text "C" at 14383.5,2138.5 h70
  text "PROJECT TITLE:" at 11343.5,277.5 h45
  text ".PRJ_Title" at 11393.5,144.17 h70
  text "DESIGNED FOR:" at 11343.5,-23.5 h45
  text ".PRJ_Customer" at 11393.5,-163.5 h70
  text "D" at -416.5,-231.5 h70
  text "D" at 14383.5,-231.5 h70
  text "FILE NAME:" at 11343.5,-323.5 h45
  text ".PCB_File_Name_No_Path" at 11393.5,-443.5 h70
  text "Texas Instruments (TI) and/or its licensors do not warrant the accuracy or completeness of this specification" at 6374,-605.34 h45
  text "ENGINEER:" at 11343.5,-613.5 h45
  text "LAYOUT BY:" at 12848.5,-613.5 h45
  text "or any information contained therein. TI and/or its licensors do not warrant that this design will meet" at 6329.01,-718 h45
  text ".PRJ_Engineer" at 11393.5,-768.49 h70
  text ".PCB_Layout" at 12899,-768.49 h70
  text "the specifications, will be suitable for your application or fit for any particular purpose, or will operate in" at 6329.01,-830.67 h45
  text ".Layer_Name" at 577,-858.49 h60
  text "ALTIUM DESIGNER VERSION:" at 12848.5,-923.5 h45
  text "an implementation. TI and/or its licensors do not warrant that the design is production worthy. You should" at 6329.01,-943.33 h45
  text "completely validate and test your design implementation to confirm the system functionality for your application." at 6374,-1056 h45
  text ".print_Scale" at 11393.5,-1056.83 h70
  text ".Application_BuildNumber" at 12899,-1056.83 h70
  text "1" at 739.84,-1263.5 h70
  text "2" at 3235.5,-1263.5 h70
  text "3" at 5724.84,-1263.5 h70
  text "4" at 8231.51,-1263.5 h70
  text "5" at 10730.5,-1263.5 h70
  text "6" at 13235.5,-1263.5 h70
M10 Fab Notes:
  drawing of 185 lines, arcs and shapes, not listed
  text "DESIGN INFORMATION" at 12381.02,5910 h60
  text "MIN. TRACK WIDTH:" at 11736.46,5730 h60
  text "8" at 12832.7,5730 h60
  text "MIL" at 12987.46,5730 h60
  text "MIN. CLEARANCE:" at 11736.46,5598 h60
  text "0.2" at 12772.7,5598 h60
  text "mm" at 12987.46,5598 h60
  text "MIN. VIA PAD SIZE:" at 11736.46,5466 h60
  text "24" at 12802.71,5466 h60
  text "MIL" at 12987.46,5466 h60
  text "0.05mm (2MIL)" at 12431.46,5324.29 h60
  text "MINIMUM ANNULAR RING" at 11407.23,5320 h60
  text "EXTERNAL" at 13139.46,5320 h60
  text "PER" at 11607.23,5202 h60
  text "IPC-D-275 CLASS 2 LEVEL C" at 11827.23,5202 h60
  text "MIL, HOLES" at 13315.46,5089.71 h60
  text "+/-" at 12923,5089 h60
  text "+/-" at 13777,5089 h60
  text "REGISTRATION TOLERANCES:" at 11407.23,5084 h60
  text "METAL" at 12607,5084 h60
  text "5" at 13183.2,5084 h60
  text "3" at 14016.2,5084 h60
  text "MIL" at 14132.46,5084 h60
  text "MATERIAL:" at 11332.46,4874.54 h60
  text "FR-4 High Tg" at 12318.9,4734.21 h60
  text "FR-408" at 11753.46,4725.64 h60
  text "X" at 12165.46,4725.64 h60
  text "OTHER" at 13241.46,4725.64 h60
  text "62 MIL (1.6mm) +/-10%" at 12073.56,4562.92 h60
  text "THICKNESS:" at 11407.23,4558.64 h60
  text "X" at 11945.4,4558.64 h60
  text "OTHER" at 13358.46,4558.64 h60
  text "TOLERANCE:" at 11407.23,4400.64 h60
  text "X" at 12246.53,4400.64 h60
  text "ANSI IPC-6012 TYPE 3 CLASS 2" at 12433.48,4400.64 h60
  text "OTHER +/-" at 12433.46,4244.64 h60
  text "BOW & TWIST:" at 11407.23,4087.64 h60
  text "X" at 12246.53,4087.64 h60
  text "ANSI IPC-6012 TYPE 3 CLASS 2" at 12433.48,4087.64 h60
  text "OTHER +/-" at 12433.46,3929.13 h60
  text "DRILLING:" at 11332.46,3790.64 h60
  text "REFERENCE:" at 11407.23,3673.64 h60
  text "X" at 12055.46,3673.64 h60
  text "AS SHOWN" at 12242.46,3673.64 h60
  text "X" at 12956.46,3673.64 h60
  text "NC_DRILL FILES" at 13093.46,3673.64 h60
  text "PTH MIN COPPER THICKNESS:" at 11407.23,3515.64 h60
  text "X" at 12757.46,3515.64 h60
  text "1MIL" at 12894.46,3515.64 h60
  text "OTHER" at 13391.46,3515.64 h60
  text "BOARD FINISH:" at 11332.46,3356.64 h60
  text "SILKSCREEN:" at 11487.68,3238.64 h60
  text "X" at 12436.46,3238.64 h60
  text "TOP" at 12562.46,3238.64 h60
  text "X" at 12946.46,3238.64 h60
  text "BOTTOM" at 13073.46,3238.64 h60
  text "X" at 12440,3075 h60
  text "SILKSCREEN COLOR:" at 11487.68,3071.64 h60
  text "WHITE" at 12562.46,3071.64 h60
  text "OTHER" at 13073.46,3071.64 h60
  text "SOLDER RESIST COLOR:" at 11487.68,2901.64 h60
  text "GREEN" at 12182.46,2742.44 h60
  text "BLUE" at 12773.46,2742.44 h60
  text "OTHER" at 13311.46,2742.44 h60
  text "X" at 13155,2740 h60
  text "RED" at 13700,2735 h60
  text "IMMERSION GOLD (ENIG)" at 12393.46,2553.92 h60
  text "ENEPIG" at 13731,2550.64 h60
  text "SURFACE FINISH:" at 11332.46,2549.64 h60
  text "X" at 12206.51,2549.64 h60
  text "IMM. TIN/SILVER OR EQUIV" at 11662,2392.64 h60
  text "OTHER" at 13093.46,2392.64 h60
  text "ARRAY/PANEL:" at 11332.46,2213.64 h60
  text "CUT AND TRIM PER MECH LAYER 1" at 12393.46,2209.35 h60
  text "N.C. ROUTE" at 12393.46,2057.64 h60
  text "X" at 13072.46,2057.64 h60
  text "V. SCORE" at 13259.46,2057.64 h60
  text "CERTIFICATION:" at 11332.46,1920.64 h60
  text "MATERIALS AND WORKMANSHIP FOR ALL PCBS" at 12057.46,1920.64 h60
  text "TO MEET OR EXCEED THE REQUIREMENTS OF:" at 12057.46,1822.64 h60
  text "X" at 11683.96,1686.13 h60
  text "ANSI IPC-A-600F CLASS ->" at 11822.96,1686.13 h60
  text "X" at 13462.02,1686.13 h60
  text "2" at 13580.96,1686.14 h60
  text "1" at 13265.96,1684.64 h60
  text "3" at 13934.96,1684.64 h60
  text "X" at 11686.02,1526.64 h60
  text "UL 94V-0" at 11822.96,1526.64 h60
  text "X" at 12498.02,1526.64 h60
  text "RoHS" at 12634.96,1526.64 h60
  text "OTHER" at 13279.36,1526.64 h60
  text "PER ORDER" at 13676.42,1526.64 h60
  text "ADDITIONAL REQUIREMENTS:" at 11332.46,1385.64 h60
  text "MICROSECTION:" at 11407.23,1270.64 h60
  text "YES" at 12312.96,1270.64 h60
  text "REQUIRED" at 13174.46,1114.49 h60
  text "BARE BOARD ELEC. TEST:" at 11407.23,1111.64 h60
  text "NONE" at 12712.96,1111.64 h60
  text "X" at 13047.46,1111.64 h60
  text "PER ORDER" at 13766.46,1111.64 h60
  text "MANUFACTURER'S UL:" at 11407.23,954.64 h60
  text "RAIL" at 12572.96,950.35 h60
  text "METAL" at 13064.77,950.35 h60
  text "X" at 13440,950 h60
  text "SILK" at 13576.46,950.35 h60
  text ".Layer_Name" at 577,-858.49 h60
M11 Gerber Information:
  lines w10: -292,-930.17 6308,-930.17 ; -292,-726.83 6310,-726.83 ; -292,-523.5 -292,-1133.5 3713,-1133.5 6310,-1133.5 6310,-523.5 -291.5,-523.5 -291.5,-1133.5 1284,-1133.5 ; 2173,-1133.5 2173,-523.5 ; 3440,-726.83 3440,-523.5 ; 4280,-726.83 4280,-523.5 ; 4902,-1140 4902,-937.17
  text "ALL ARTWORK VIEWED FROM TOP SIDE" at -228.5,-655.67 h60
  text "BOARD #:" at 2248,-655.67 h60
  text ".PRJ_Number" at 2793.5,-655.67 h60
  text "REV:" at 3638,-655.67 h60
  text ".PCB_Rev" at 3929.5,-655.67 h60
  text "SVN REV:" at 4476,-655.67 h60
  text ".VersionControl_RevNumber" at 4982,-655.67 h60
  text "LAYER NAME =" at -228.5,-858.49 h60
  text "PLOT NAME =" at -228.5,-1064.34 h60
  text ".plot_File_Name" at 577,-1064.34 h60
  text "GENERATED    :" at 2250,-1064.34 h60
  text ".Print_Date" at 3119.5,-1064.34 h60
  text ".Print_Time" at 3848.5,-1064.34 h60
  text "TEXAS INSTRUMENTS" at 5113,-1064.34 h60
M12 Stackup:
  drawing of 191 lines, arcs and shapes, not listed
  text "Layer" at 9790.58,7830 h60
  text "Name" at 10200.49,7830 h60
  text "Material" at 11130.23,7830 h60
  text "Thickness" at 11990,7830 h60
  text "Constant" at 12639.84,7830 h60
  text "Board Layer Stack" at 13209.7,7830 h60
  text "1" at 9790.58,7710 h60
  text "Top Overlay" at 10200.49,7710 h60
  text "2" at 9790.58,7590 h60
  text "Top Solder" at 10200.49,7590 h60
  text "Solder Resist" at 11130.23,7590 h60
  text "0.40mil" at 11990,7590 h60
  text "3.5" at 12639.84,7590 h60
  text "3" at 9790.58,7470 h60
  text "Top Layer" at 10200.49,7470 h60
  text "Copper" at 11130.23,7470 h60
  text "1.40mil" at 11990,7470 h60
  text "4" at 9790.58,7350 h60
  text "Dielectric1" at 10200.49,7350 h60
  text "FR-4" at 11130.23,7350 h60
  text "59.20mil" at 11990,7350 h60
  text "4.8" at 12639.84,7350 h60
  text "5" at 9790.58,7230 h60
  text "Bottom Layer" at 10200.49,7230 h60
  text "Copper" at 11130.23,7230 h60
  text "1.40mil" at 11990,7230 h60
  text "6" at 9790.58,7110 h60
  text "Bottom Solder" at 10200.49,7110 h60
  text "Solder Resist" at 11130.23,7110 h60
  text "0.40mil" at 11990,7110 h60
  text "3.5" at 12639.84,7110 h60
  text "7" at 9790.58,6990 h60
  text "Bottom Overlay" at 10200.49,6990 h60
  text ".Layer_Name" at 577,-858.49 h60
M13 Component Bodies Top:
  text ".Layer_Name" at 577,-858.49 h60
M14 Component Bodies Bottom:
  text ".Layer_Name" at 577,-858.49 h60
M15 Courtyards Top:
  text ".Layer_Name" at 577,-858.49 h60
M16 Courtyards Bottom:
  text ".Layer_Name" at 577,-858.49 h60
Drill Drawing:
  circle w1: c5572.72,3071.72 r14.93
  circle w1: c5572.72,3071.72 r24.89
  circle w1: c5572.72,2474.44 r24.89
  lines w1: 5547.83,1864.72 5560.27,1864.72 5560.27,1852.28 5585.16,1852.28 5585.16,1864.72 5597.6,1864.72 5597.6,1889.61 5585.16,1889.61 5585.16,1902.05 5560.27,1902.05 5560.27,1889.61 5547.83,1889.61 5547.83,1864.72 ; 5547.83,2001.6 5572.72,2014.04 5597.6,2001.6 5585.16,2026.48 5597.6,2051.37 5572.72,2038.93 5547.83,2051.37 5560.27,2026.48 5547.83,2001.6 ; 5547.83,2175.8 5572.72,2150.92 5597.6,2175.8 5572.72,2200.69 5547.83,2175.8 ; 5547.83,2312.68 5560.27,2312.68 5572.72,2300.24 5585.16,2312.68 5597.6,2312.68 5585.16,2325.12 5597.6,2337.57 5585.16,2337.57 5572.72,2350.01 5560.27,2337.57 5547.83,2337.57 5560.27,2325.12 5547.83,2312.68 ; 5547.83,2648.65 5597.6,2648.65 5572.72,2598.88 5547.83,2648.65 ; 5547.83,2748.2 5597.6,2748.2 5597.6,2797.97 5547.83,2797.97 5547.83,2748.2 ; 5547.83,2897.52 5597.6,2897.52 5597.6,2947.29 5547.83,2947.29 5547.83,2897.52 ; 5547.83,3196.16 5547.83,3208.6 5560.27,3221.04 5547.83,3233.49 5547.83,3245.93 5560.27,3245.93 5572.72,3233.49 5585.16,3245.93 5597.6,3245.93 5597.6,3233.49 5585.16,3221.04 5597.6,3208.6 5597.6,3196.16 5585.16,3196.16 5572.72,3208.6 5560.27,3196.16 5547.83,3196.16 ; 5557.78,2907.47 5587.65,2907.47 5587.65,2937.33 5557.78,2937.33 5557.78,2907.47
  lines w12: 5480,1807.48 7598.02,1807.48 ; 5480,3300.68 7598.02,3300.68 ; 5850.36,1658.16 5850.36,3450 ; 6207.36,1658.16 6207.36,3450 ; 6868.93,1658.16 6868.93,3450 ; 7153.07,1658.16 7153.07,3450 ; 5480,1658.16 7598.02,1658.16 7598.02,3450 5480,3450 5480,1658.16
  text "Symbol" at 5569.59,3345.48 h72
  text "Quantity" at 5895.16,3345.48 h72
  text "Finished Hole Size" at 6252.16,3345.48 h72
  text "Plated" at 6913.72,3345.48 h72
  text "Hole Type" at 7197.86,3345.48 h72
  text "4" at 5895.16,3196.16 h60
  text "7.87mil (0.200mm)" at 6252.16,3196.16 h60
  text "PTH" at 6913.72,3196.16 h60
  text "Round" at 7197.86,3196.16 h60
  text "31" at 5895.16,3046.84 h60
  text "18.00mil (0.457mm)" at 6252.16,3046.84 h60
  text "PTH" at 6913.72,3046.84 h60
  text "Round" at 7197.86,3046.84 h60
  text "2" at 5895.16,2897.52 h60
  text "30.00mil (0.762mm)" at 6252.16,2897.52 h60
  text "PTH" at 6913.72,2897.52 h60
  text "Round" at 7197.86,2897.52 h60
  text "18" at 5895.16,2748.2 h60
  text "40.00mil (1.016mm)" at 6252.16,2748.2 h60
  text "PTH" at 6913.72,2748.2 h60
  text "Round" at 7197.86,2748.2 h60
  text "2" at 5895.16,2598.88 h60
  text "43.31mil (1.100mm)" at 6252.16,2598.88 h60
  text "PTH" at 6913.72,2598.88 h60
  text "Round" at 7197.86,2598.88 h60
  text "12" at 5895.16,2449.56 h60
  text "45.28mil (1.150mm)" at 6252.16,2449.56 h60
  text "PTH" at 6913.72,2449.56 h60
  text "Round" at 7197.86,2449.56 h60
  text "1" at 5895.16,2300.24 h60
  text "46.50mil (1.181mm)" at 6252.16,2300.24 h60
  text "PTH" at 6913.72,2300.24 h60
  text "Round" at 7197.86,2300.24 h60
  text "40" at 5895.16,2150.92 h60
  text "47.24mil (1.200mm)" at 6252.16,2150.92 h60
  text "PTH" at 6913.72,2150.92 h60
  text "Round" at 7197.86,2150.92 h60
  text "2" at 5895.16,2001.6 h60
  text "49.21mil (1.250mm)" at 6252.16,2001.6 h60
  text "PTH" at 6913.72,2001.6 h60
  text "Round" at 7197.86,2001.6 h60
  text "1" at 5895.16,1852.28 h60
  text "59.06mil (1.500mm)" at 6252.16,1852.28 h60
  text "PTH" at 6913.72,1852.28 h60
  text "Round" at 7197.86,1852.28 h60
  text "113 Total" at 5895.16,1702.96 h60
  text ".Layer_Name" at 577,-858.49 h60

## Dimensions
0,-400 to 1000,-400 on M2 Board Dimensions
0,0 to 4000,0 on Top Layer
-5.01,1500 to 0,0 on Top Layer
